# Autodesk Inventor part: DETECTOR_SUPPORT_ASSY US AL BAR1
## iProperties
Shininess: 64.0
Length Units: 11272
Angle Units: 11279
Time Units: 11290
Mass Units: 11286
Length Display Precision: 3
Angle Display Precision: 2
Compacted: True
Part Number: DETECTOR_SUPPORT_ASSY US AL BAR1
Document SubType Name: Modeling
Created: 2004-08
Designer: John Blackburn
Material: ALUMINUM
Manufacturer: Standard
Standards Organization: Custom
Density: 0.0
Volumn: 0.0
Area: 0.0
PropertySet Name: Model Information
Control State: 0
Master: False
Checked Out: False
Author: John Blackburn
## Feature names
1. ExtrusionMidplane1
2. AM_HOLE_SI0029_1 [Hole]
3. Rectangular Pattern1
